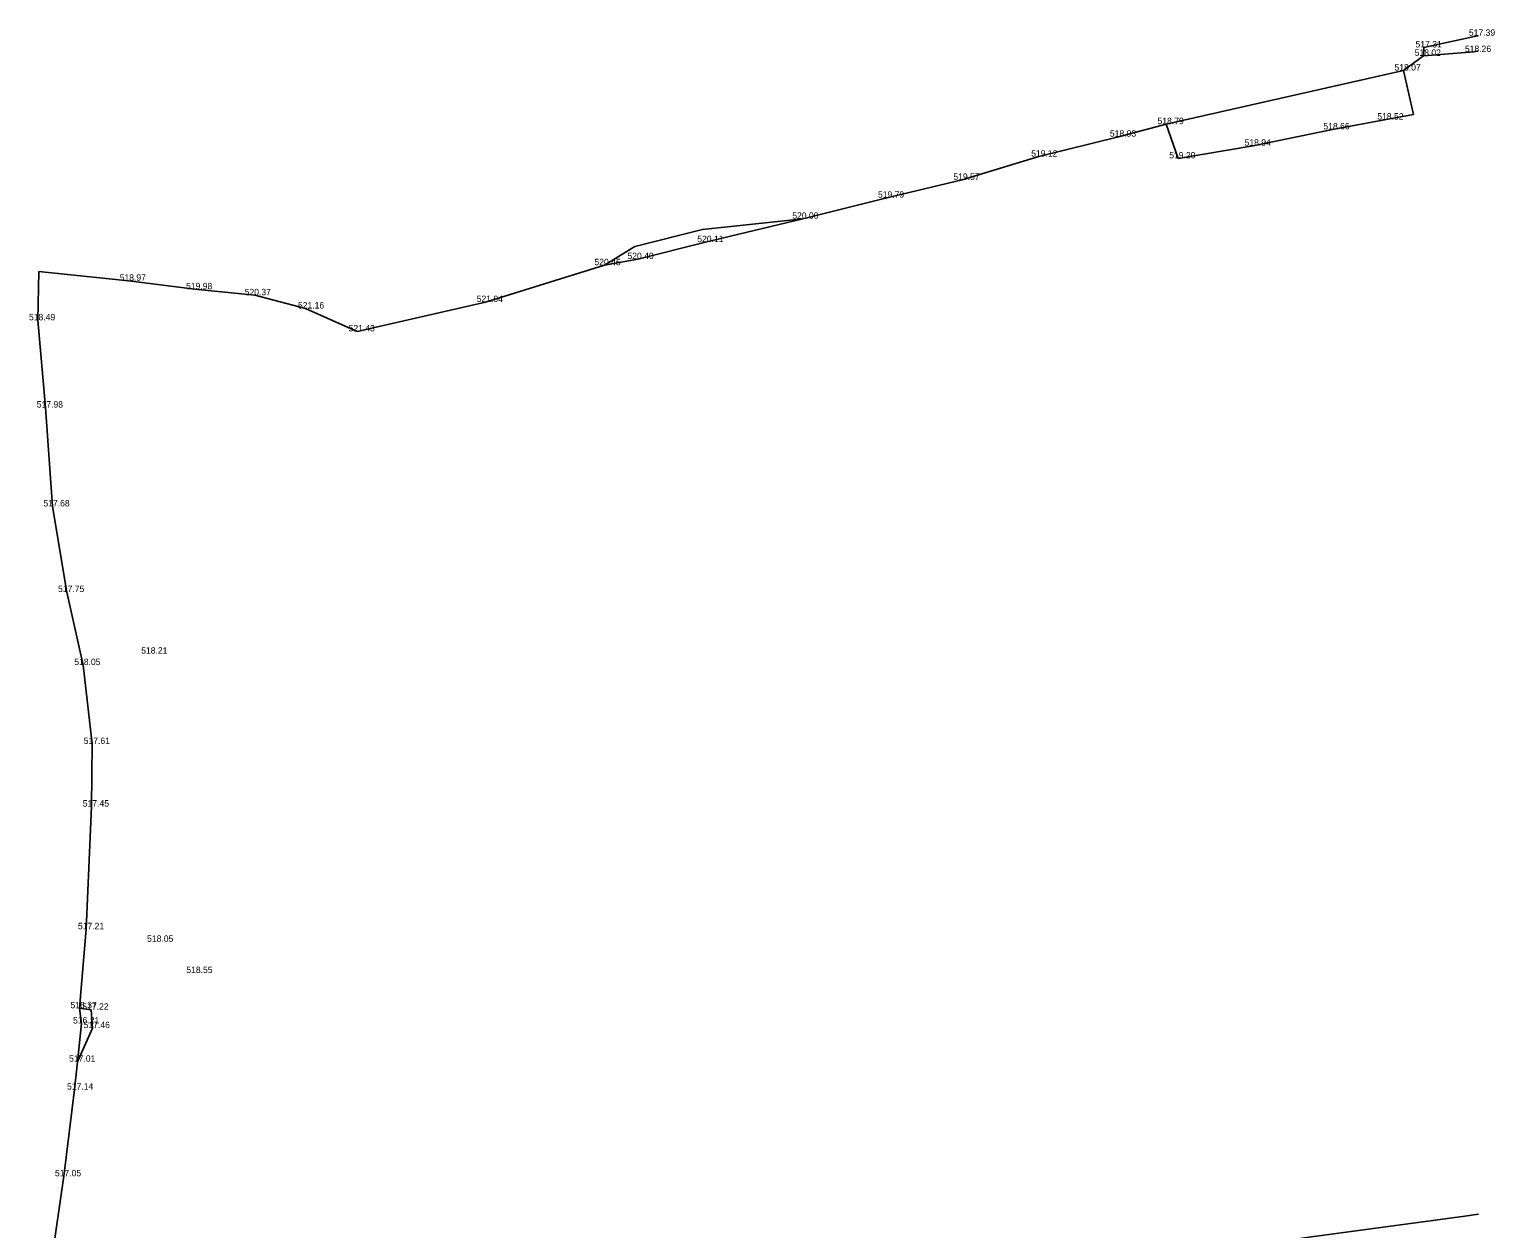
# Model space of a CAD drawing. Extents: x -669642 to -669119, y -1131006 to -1130466.
# Drawn here: x -669359.5 to -669188.2, y -1130805.7 to -1130665.5 of the extents above; entities that cross this region are included whole.
import ezdxf

# ---------------------------------------------------------------- set-up
doc = ezdxf.new("R2010")
doc.units = 0
for name, color, linetype in [('G_Bod_tecka', 7, 'Continuous'), ('G_Bod_vyska', 7, 'Continuous'), ('G_Breh_Teren', 7, 'Continuous'), ('G_Ploty', 7, 'Continuous')]:
    doc.layers.add(name, color=color, linetype=linetype)

msp = doc.modelspace()

# ---------------------------------------------------------------- linework, layer by layer
at = {"layer": 'G_Bod_tecka'}
for p, q in [((-669190.18, -1130666.28), (-669190.18, -1130666.28)), ((-669196.5, -1130668.62), (-669196.5, -1130668.62)), ((-669196.48, -1130667.64), (-669196.48, -1130667.64)), ((-669190.63, -1130668.17), (-669190.63, -1130668.17)), ((-669198.86, -1130670.34), (-669198.86, -1130670.34)), ((-669200.89, -1130676.07), (-669200.89, -1130676.07)), ((-669226.59, -1130676.61), (-669226.59, -1130676.61)), ((-669207.16, -1130677.22), (-669207.16, -1130677.22)), ((-669232.16, -1130678.07), (-669232.16, -1130678.07)), ((-669216.41, -1130679.13), (-669216.41, -1130679.13)), ((-669241.5, -1130680.4), (-669241.5, -1130680.4)), ((-669225.19, -1130680.61), (-669225.19, -1130680.61)), ((-669250.46, -1130683.12), (-669250.46, -1130683.12)), ((-669259.27, -1130685.21), (-669259.27, -1130685.21)), ((-669269.09, -1130687.67), (-669269.09, -1130687.67)), ((-669280.45, -1130690.4), (-669280.45, -1130690.4)), ((-669292.26, -1130693.1), (-669292.26, -1130693.1)), ((-669288.38, -1130692.38), (-669288.38, -1130692.38)), ((-669347.95, -1130694.92), (-669347.95, -1130694.92)), ((-669340.18, -1130695.91), (-669340.18, -1130695.91)), ((-669333.16, -1130696.61), (-669333.16, -1130696.61)), ((-669327.23, -1130698.16), (-669327.23, -1130698.16)), ((-669306.18, -1130697.4), (-669306.18, -1130697.4)), ((-669358.55, -1130699.54), (-669358.55, -1130699.54)), ((-669321.18, -1130700.84), (-669321.18, -1130700.84)), ((-669357.64, -1130709.74), (-669357.64, -1130709.74)), ((-669356.84, -1130721.3), (-669356.84, -1130721.3)), ((-669355.15, -1130731.31), (-669355.15, -1130731.31)), ((-669345.49, -1130738.51), (-669345.49, -1130738.51)), ((-669353.24, -1130739.85), (-669353.24, -1130739.85)), ((-669352.2, -1130749.07), (-669352.2, -1130749.07)), ((-669352.26, -1130756.39), (-669352.26, -1130756.39)), ((-669352.89, -1130770.73), (-669352.89, -1130770.73)), ((-669344.72, -1130772.2), (-669344.72, -1130772.2)), ((-669340.15, -1130775.85), (-669340.15, -1130775.85)), ((-669353.68, -1130779.97), (-669353.68, -1130779.97)), ((-669352.31, -1130780.14), (-669352.31, -1130780.14)), ((-669353.45, -1130781.75), (-669353.45, -1130781.75)), ((-669352.14, -1130782.29), (-669352.14, -1130782.29)), ((-669353.9, -1130786.22), (-669353.9, -1130786.22)), ((-669354.24, -1130789.48), (-669354.24, -1130789.48)), ((-669355.5, -1130799.61), (-669355.5, -1130799.61))]:
    msp.add_line(p, q, dxfattribs=at)
at = {"layer": 'G_Breh_Teren'}
for points in [[(-669196.5, -1130668.62), (-669190.63, -1130668.17)], [(-669190.63, -1130668.17), (-669190.09, -1130668.04)], [(-669226.59, -1130676.61), (-669198.86, -1130670.34)], [(-669280.81, -1130688.94), (-669269.09, -1130687.67)], [(-669288.74, -1130690.92), (-669280.81, -1130688.94)], [(-669292.26, -1130693.1), (-669288.74, -1130690.92)], [(-669352.31, -1130780.14), (-669353.68, -1130779.97)], [(-669352.14, -1130782.29), (-669352.31, -1130780.14)], [(-669352.14, -1130782.29), (-669353.9, -1130786.22)]]:
    msp.add_lwpolyline(points, dxfattribs=at)
at = {"layer": 'G_Ploty'}
for p, q in [((-669196.48, -1130667.64), (-669190.18, -1130666.28)), ((-669198.86, -1130670.34), (-669196.5, -1130668.62)), ((-669196.5, -1130668.62), (-669196.48, -1130667.64)), ((-669197.69, -1130675.48), (-669198.86, -1130670.34)), ((-669232.16, -1130678.07), (-669226.59, -1130676.61)), ((-669226.59, -1130676.61), (-669225.19, -1130680.61)), ((-669216.41, -1130679.13), (-669207.16, -1130677.22)), ((-669241.5, -1130680.4), (-669232.16, -1130678.07)), ((-669225.19, -1130680.61), (-669216.41, -1130679.13)), ((-669250.46, -1130683.12), (-669241.5, -1130680.4)), ((-669259.27, -1130685.21), (-669250.46, -1130683.12)), ((-669269.09, -1130687.67), (-669259.27, -1130685.21)), ((-669280.45, -1130690.4), (-669269.09, -1130687.67)), ((-669288.38, -1130692.38), (-669280.45, -1130690.4)), ((-669306.18, -1130697.4), (-669292.26, -1130693.1)), ((-669292.26, -1130693.1), (-669288.38, -1130692.38)), ((-669358.42, -1130693.83), (-669347.95, -1130694.92)), ((-669347.95, -1130694.92), (-669340.18, -1130695.91)), ((-669340.18, -1130695.91), (-669333.16, -1130696.61)), ((-669333.16, -1130696.61), (-669327.23, -1130698.16)), ((-669327.23, -1130698.16), (-669321.18, -1130700.84)), ((-669321.18, -1130700.84), (-669306.18, -1130697.4)), ((-669352.26, -1130756.39), (-669352.2, -1130749.07)), ((-669352.89, -1130770.73), (-669352.26, -1130756.39)), ((-669353.68, -1130779.97), (-669352.89, -1130770.73)), ((-669353.45, -1130781.75), (-669353.68, -1130779.97)), ((-669353.9, -1130786.22), (-669353.45, -1130781.75)), ((-669354.24, -1130789.48), (-669353.9, -1130786.22)), ((-669355.5, -1130799.61), (-669354.24, -1130789.48)), ((-669357.47, -1130813.17), (-669355.5, -1130799.61))]:
    msp.add_line(p, q, dxfattribs=at)
for points in [[(-669190.18, -1130666.28), (-669190.09, -1130666.25)], [(-669207.16, -1130677.22), (-669200.89, -1130676.07), (-669197.69, -1130675.48)], [(-669352.2, -1130749.07), (-669353.24, -1130739.85), (-669355.15, -1130731.31), (-669356.84, -1130721.3), (-669357.64, -1130709.74), (-669358.55, -1130699.54), (-669358.42, -1130693.83)], [(-669221.97, -1130808.43), (-669209.59, -1130806.71), (-669191.68, -1130804.27), (-669190.09, -1130804.06)]]:
    msp.add_lwpolyline(points, dxfattribs=at)

# ---------------------------------------------------------------- texts
at = {"layer": 'G_Bod_vyska'}
for s, p in [('517.39', (-669191.2, -1130666.28)), ('517.31', (-669197.44, -1130667.64)), ('518.26', (-669191.67, -1130668.17)), ('518.02', (-669197.54, -1130668.62)), ('518.07', (-669199.9, -1130670.34)), ('518.79', (-669227.61, -1130676.61)), ('518.52', (-669201.91, -1130676.07)), ('518.93', (-669233.18, -1130678.07)), ('518.66', (-669208.21, -1130677.22)), ('518.94', (-669217.43, -1130679.13)), ('519.12', (-669242.38, -1130680.4)), ('519.20', (-669226.24, -1130680.61)), ('519.57', (-669251.48, -1130683.12)), ('519.79', (-669260.3, -1130685.21)), ('520.00', (-669270.32, -1130687.67)), ('520.11', (-669281.43, -1130690.4)), ('520.45', (-669293.45, -1130693.1)), ('520.40', (-669289.59, -1130692.38)), ('518.97', (-669348.97, -1130694.92)), ('519.98', (-669341.21, -1130695.91)), ('520.37', (-669334.35, -1130696.61)), ('521.04', (-669307.22, -1130697.4)), ('521.16', (-669328.12, -1130698.16)), ('518.49', (-669359.57, -1130699.54)), ('521.43', (-669322.2, -1130700.84)), ('517.98', (-669358.66, -1130709.74)), ('517.68', (-669357.88, -1130721.3)), ('517.75', (-669356.17, -1130731.31)), ('518.21', (-669346.45, -1130738.51)), ('518.05', (-669354.28, -1130739.85)), ('517.61', (-669353.17, -1130749.07)), ('517.45', (-669353.28, -1130756.39)), ('517.21', (-669353.85, -1130770.73)), ('518.05', (-669345.76, -1130772.2)), ('518.55', (-669341.17, -1130775.85)), ('516.37', (-669354.72, -1130779.97)), ('517.22', (-669353.33, -1130780.14)), ('516.21', (-669354.42, -1130781.75)), ('517.46', (-669353.18, -1130782.29)), ('517.01', (-669354.88, -1130786.22)), ('517.14', (-669355.12, -1130789.48)), ('517.05', (-669356.54, -1130799.61))]:
    msp.add_text(s, height=0.75, dxfattribs=at).set_placement(p)

doc.saveas('drawing.dxf')
